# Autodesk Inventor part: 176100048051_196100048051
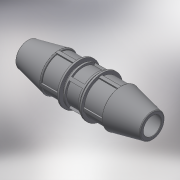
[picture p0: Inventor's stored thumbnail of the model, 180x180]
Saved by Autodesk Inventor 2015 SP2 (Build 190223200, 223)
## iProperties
Created: 2016-12
Part Number: 176100048051_196100048051
Material: Generic
Description: PLASSON UNIVERSAL SLIP REPAIR COUPLER 48-51 SERIES 17
Document SubType Name: Modeling
Designer: KIM
Mass: 305.707 g
Surface Area: 640.661 cm^2
Volume: 305.707 cm^3
Density: 1 g/cm^3
Appearance: Default
Author: KIM
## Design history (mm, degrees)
derived "17610.ipt"
feature "Solid1::17610.ipt"
tag "TaggingFeature1"
body "Solid1"
other parameters: "d5" = 158, "d11" = 39.5, "d12" = 3.16, "d13" = 71.4, "d14" = 67.5, "d15" = 51, "d16" = 49.98, "d17" = 80.8, "d20" = 85.85, "d21" = 80 deg, "d22" = 38.57143, "d23" = 0, "d25" = 360 deg, "d31" = 31.6, "d32" = 90.9, "d33" = 80 deg, "d34" = 40 deg, "d35" = 80.8, "d36" = 12.64, "d37" = 0, "d39" = 360 deg, "d41" = 2.7, "d43" = 360 deg, "d48" = 2.55, "d52" = 1.01, "d55" = 101, "d56" = 92.92, "d_" = 51, "E_" = 101, "l_" = 158
